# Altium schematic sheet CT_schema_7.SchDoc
size 251 x 159 mm
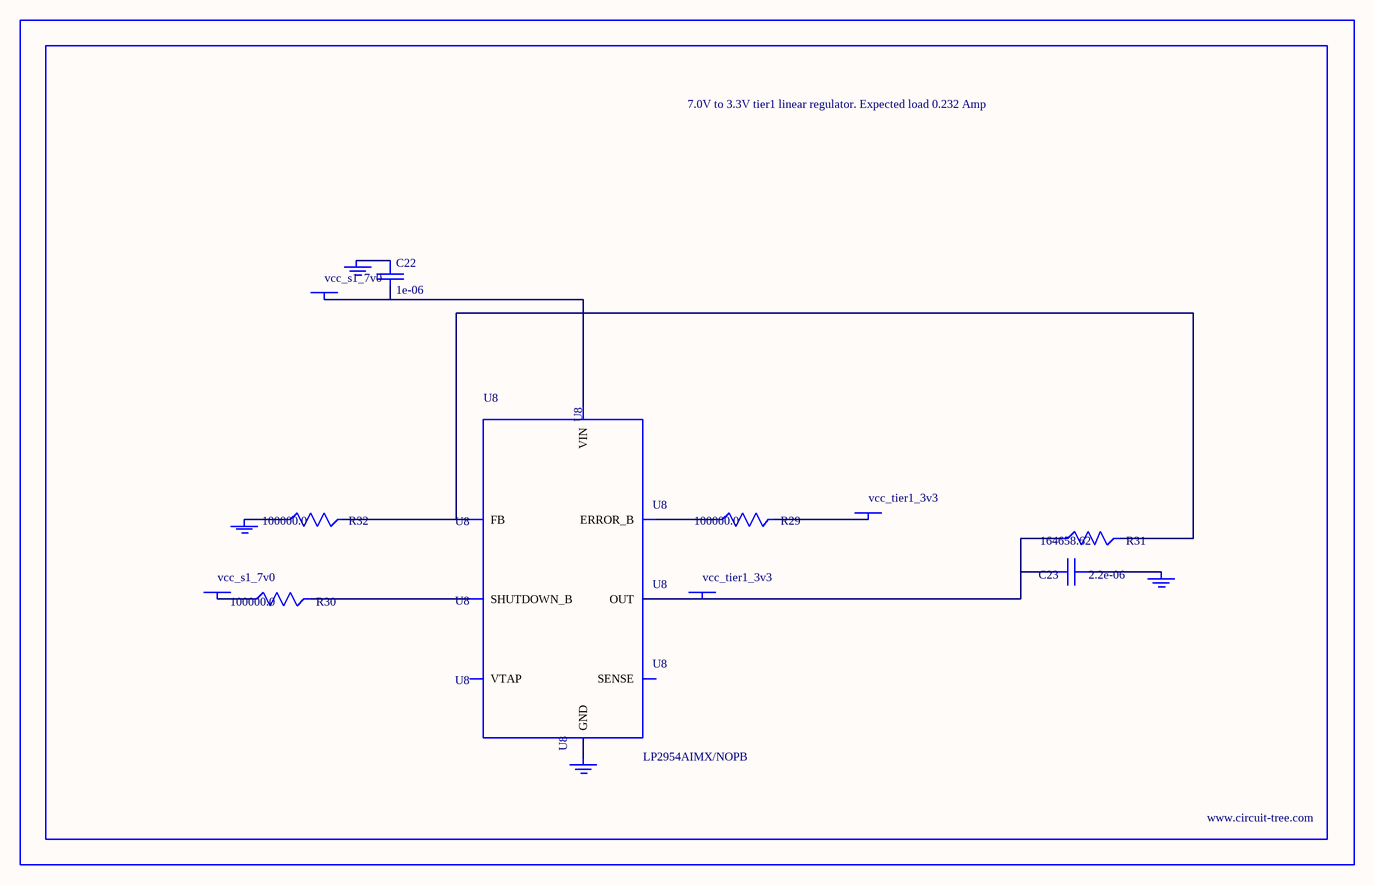
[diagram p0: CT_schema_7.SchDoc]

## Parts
BORDER6  (no value)
C22  1e-06  [EXV-9B]
C23  2.2e-06  [EXV-9B]
GND_INSTANCE_6_0  (no value)
GND_INSTANCE_6_1  (no value)
GND_INSTANCE_6_2  (no value)
GND_INSTANCE_6_3  (no value)
POWER_INSTANCE_6_0  vcc_s1_7v0
POWER_INSTANCE_6_1  vcc_tier1_3v3
POWER_INSTANCE_6_2  vcc_s1_7v0
POWER_INSTANCE_6_3  vcc_tier1_3v3
R29  100000.0  [R0603]
R30  100000.0  [R0603]
R31  164658.62  [R0603]
R32  100000.0  [R0603]
U8  LP2954AIMX/NOPB  [LP2954]

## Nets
NetC22_1: C22.1 GND_INSTANCE_6_2.0(GND)
NetC22_2: C22.2 POWER_INSTANCE_6_2.0(PWR) U8.8(VIN)
NetC23_1: C23.1 GND_INSTANCE_6_0.0(GND)
NetC23_2: C23.2 POWER_INSTANCE_6_3.0(PWR) R31.1 U8.1(OUT)
NetGND_INSTANCE_6_1_0: GND_INSTANCE_6_1.0(GND) R32.1
NetGND_INSTANCE_6_3_0: GND_INSTANCE_6_3.0(GND) U8.4(GND)
NetPOWER_INSTANCE_6_0_0: POWER_INSTANCE_6_0.0(PWR) R30.1
NetPOWER_INSTANCE_6_1_0: POWER_INSTANCE_6_1.0(PWR) R29.2
NetR29_1: R29.1 U8.5(ERROR_B)
NetR30_2: R30.2 U8.3(SHUTDOWN_B)
NetR31_2: R31.2 R32.2 U8.7(FB)

Not connected (* = marked no-connect by the designer): U8 2(SENSE) 6(VTAP)

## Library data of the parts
BORDER6 = BORDER_PAGE6
C22 = EDK105M050A9BAA
C23 = EDK225M050A9BAA
GND_INSTANCE_6_0-GND_INSTANCE_6_3 = GND
POWER_INSTANCE_6_0-POWER_INSTANCE_6_3 = PWR
R29 R30 R32 = RC0603JR-07100KL
R31 = R31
